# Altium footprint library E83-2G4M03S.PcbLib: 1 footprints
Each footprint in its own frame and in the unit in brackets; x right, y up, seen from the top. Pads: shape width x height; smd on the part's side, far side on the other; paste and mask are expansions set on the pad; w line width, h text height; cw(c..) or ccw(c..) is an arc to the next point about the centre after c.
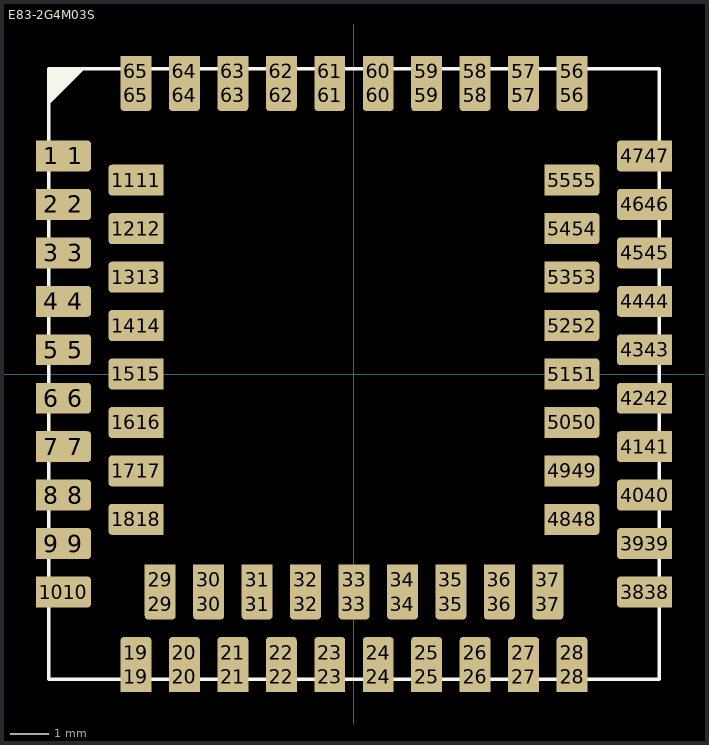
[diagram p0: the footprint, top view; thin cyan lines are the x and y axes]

## E83-2G4M03S [mm]
pads (130):
  rect 0.81x0.81 smd mask+0.102: 1(-7.935,5.715)
  rrect22% 0.81x0.81 smd mask+0.102: 1(-7.3,5.715)
  rect 0.81x0.81 smd: 2(-7.935,4.445) 3(-7.935,3.175) 4(-7.935,1.905) 5(-7.935,0.635) 6(-7.935,-0.635) 7(-7.935,-1.905) 8(-7.935,-3.175) 9(-7.935,-4.445) 10(-7.935,-5.715) 11(-5.395,5.08) 12(-5.395,3.81) 13(-5.395,2.54) 14(-5.395,1.27) 15(-5.395,0) 16(-5.395,-1.27) 17(-5.395,-2.54) 18(-5.395,-3.81) 19(-5.715,-7.935) 20(-4.445,-7.935) 21(-3.175,-7.935) 22(-1.905,-7.935) 23(-0.635,-7.935) 24(0.635,-7.935) 25(1.905,-7.935) 26(3.175,-7.935) 27(4.445,-7.935) 28(5.715,-7.935) 29(-5.08,-5.395) 30(-3.81,-5.395) 31(-2.54,-5.395) 32(-1.27,-5.395) 33(0,-5.395) 34(1.27,-5.395) 35(2.54,-5.395) 36(3.81,-5.395) 37(5.08,-5.395) 38(7.935,-5.715) 39(7.935,-4.445) 40(7.935,-3.175) 41(7.935,-1.905) 42(7.935,-0.635) 43(7.935,0.635) 44(7.935,1.905) 45(7.935,3.175) 46(7.935,4.445) 47(7.935,5.715) 48(5.395,-3.81) 49(5.395,-2.54) 50(5.395,-1.27) 51(5.395,0) 52(5.395,1.27) 53(5.395,2.54) 54(5.395,3.81) 55(5.395,5.08) 56(5.715,7.935) 57(4.445,7.935) 58(3.175,7.935) 59(1.905,7.935) 60(0.635,7.935) 61(-0.635,7.935) 62(-1.905,7.935) 63(-3.175,7.935) 64(-4.445,7.935) 65(-5.715,7.935)
  rrect22% 0.81x0.81 smd paste-0.05 mask+0.102: 2(-7.3,4.445) 3(-7.3,3.175) 4(-7.3,1.905) 5(-7.3,0.635) 6(-7.3,-0.635) 7(-7.3,-1.905) 8(-7.3,-3.175) 9(-7.3,-4.445) 10(-7.3,-5.715) 11(-6.03,5.08) 12(-6.03,3.81) 13(-6.03,2.54) 14(-6.03,1.27) 15(-6.03,0) 16(-6.03,-1.27) 17(-6.03,-2.54) 18(-6.03,-3.81) 19(-5.715,-7.3) 20(-4.445,-7.3) 21(-3.175,-7.3) 22(-1.905,-7.3) 23(-0.635,-7.3) 24(0.635,-7.3) 25(1.905,-7.3) 26(3.175,-7.3) 27(4.445,-7.3) 28(5.715,-7.3) 29(-5.08,-6.03) 30(-3.81,-6.03) 31(-2.54,-6.03) 32(-1.27,-6.03) 33(0,-6.03) 34(1.27,-6.03) 35(2.54,-6.03) 36(3.81,-6.03) 37(5.08,-6.03) 38(7.3,-5.715) 39(7.3,-4.445) 40(7.3,-3.175) 41(7.3,-1.905) 42(7.3,-0.635) 43(7.3,0.635) 44(7.3,1.905) 45(7.3,3.175) 46(7.3,4.445) 47(7.3,5.715) 48(6.03,-3.81) 49(6.03,-2.54) 50(6.03,-1.27) 51(6.03,0) 52(6.03,1.27) 53(6.03,2.54) 54(6.03,3.81) 55(6.03,5.08) 56(5.715,7.3) 57(4.445,7.3) 58(3.175,7.3) 59(1.905,7.3) 60(0.635,7.3) 61(-0.635,7.3) 62(-1.905,7.3) 63(-3.175,7.3) 64(-4.445,7.3) 65(-5.715,7.3)
Top Overlay:
  lines w0.1: -7.873,7.492 -8,7.365 ; -7.492,8 -8,7.492 -7.619,7.873 -7.619,8 ; -6.986,8 -7.111,8 ; -8,7.365 -8,7.238 -7.238,8 ; -8,7.365 -8,7.746 ; -8,7.365 -7.365,8 -7.619,8 ; -8,7.746 -8,8 ; -8,7.746 -8,8 ; -8,7.746 -7.746,8 ; -8,8 -7.619,8 ; -8,8 -7.873,7.873 ; -8,8 -7.746,8 ; -8,8 -8,7.619 -7.619,8 ; -8,8 -8,-8 8,-8 8,8 -8,8 ; -7.873,7.873 -8,7.873 -8,7.111 -7.111,8 ; -7.873,7.873 -7.873,8 -7.873,7.873 ; -7.746,8 -7.619,8 ; -7.619,8 -7.238,8 ; -7.238,8 -7.111,8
